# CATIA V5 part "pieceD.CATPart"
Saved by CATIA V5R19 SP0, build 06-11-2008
Part number: Part1
Bounding box of the stored display mesh (mm): x 0 to 200, y -100 to 100, z -20 to 114.512
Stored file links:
  D:\thinkmotion-MPB\Dropbox\CIAO82010_JCF\BOUCHEFRA\580-bouchefra\pieceD.CATPart
  D:\thinkmotion-MPB\Dropbox\CIAO82010_JCF\BOUCHEFRA\580-bouchefra\bielle.CATPart
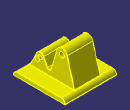
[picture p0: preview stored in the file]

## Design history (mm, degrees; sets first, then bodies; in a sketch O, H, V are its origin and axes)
Body1 (main body)
  Sketch1 on yz-plane, origin (0, 0, 0), H (0, 1, 0), V (0, 0, 1)
    line L1 (-85, -2.6124) -> (85, -2.6124)
    point P1 (-100, -2.6124)
    point P2 (100, -2.6124)
    line L2 (100, -17.6124) -> (100, -20)
    line L3 (100, -20) -> (-100, -20)
    line L4 (-100, -17.6124) -> (-100, -20)
    arc A1 centre (85, -17.6124) radius 15 from (100, -17.6124) to (85, -2.6124) ccw
    arc A2 centre (-85, -17.6124) radius 15 from (-100, -17.6124) to (-85, -2.6124) cw
    distance P1 P2 = 200
    radius A1 = 15
    radius A2 = 15
    horizontal: L1 H, L3 H
    vertical: L2 V, L4 V
    coincidence: L2 P2, L1 P2, L4 P1, L1 P1
    tangency: A1 L2, A1 L1, A2 L4, A2 L1
  Pad1: profile Sketch1, direction (1, 0, 0), length 200
  Sketch2 on end face of Pad1, origin (200, 0, 0), H (0, 1, 0), V (0, 0, 1)
    line L1 (86.0912, -2.8716) -> (58.5066, 98.9698)
    arc A1 centre (38.1943, 93.468) radius 21.0442 from (58.5066, 98.9698) to (17.9745, 99.3006) ccw
    line L2 (17.9745, 99.3006) -> (-4.1104, 22.7393)
    arc A2 centre (-11.4234, 24.8488) radius 7.6111 from (-4.1104, 22.7393) to (-18.2284, 21.4398) cw
    line L3 (-18.2284, 21.4398) -> (-32.6655, 50.2596)
    arc A3 centre (-46.3678, 43.3955) radius 15.3254 from (-32.6655, 50.2596) to (-60.1871, 50.0207) ccw
    line L4 (-60.1871, 50.0207) -> (-85.5976, -2.9828)
    line L5 (86.0912, -2.8716) -> (-85.5976, -2.9828)
    tangency: A1 L1, L2 A1, A2 L2, A3 L3, L4 A3, A2 L3
  Pad2: profile Sketch2, direction (-1, 0, 0), length 150, opposite side length -50
  Chamfer1: length 1, angle 45, on face of Pad2 from Sketch2.L1; start face of Pad2; face of Pad2 from Sketch2.L3; end face of Pad1; face of Pad1 from Sketch1.L2; start face of Pad1; face of Pad2 from Sketch2.L4; face of Pad2 from Sketch2.L2
  Sketch3 on start face of Pad2, origin (150, 44.3568, 72.5511), H (0, 1, 0), V (0, 0, 1)
    point P1 (-6.2119, 19.0472)
  Hole1: placed by Sketch3, at (150, 38.1449, 91.5983) direction (-1, 0, 0), diameter 20, through (limit type 3)
  Sketch4 on start face of Pad2, origin (150, 0, 0), H (0, 1, 0), V (0, 0, 1)
    circle A1 centre (-47.1086, 41.0288) radius 8.5
    radius A1 = 8.5
  Pad3: profile Sketch4, direction (1, 0, 0), length 10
